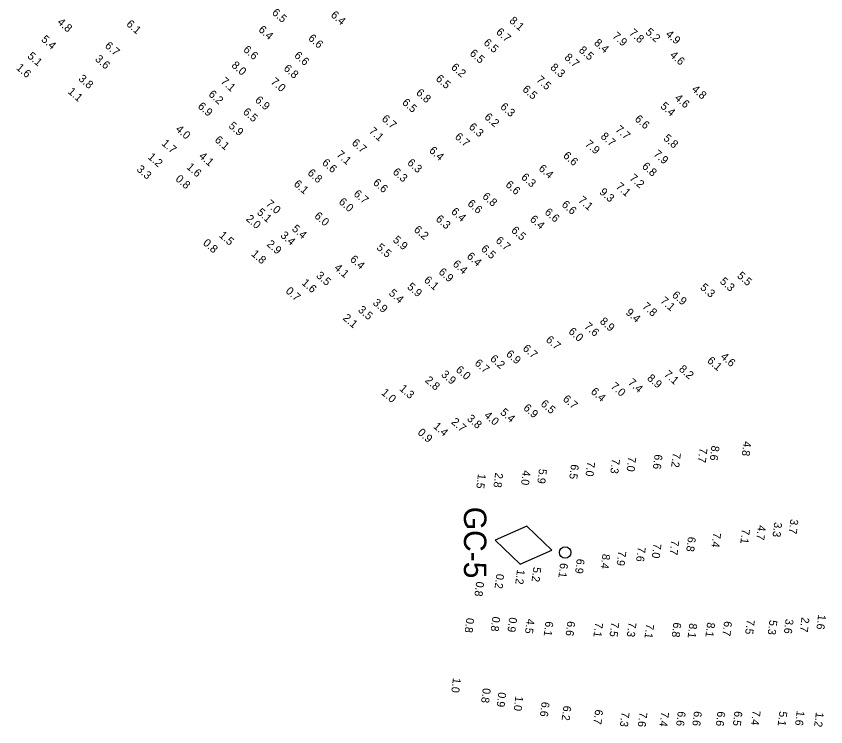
# Model space of a CAD drawing. Extents: x 815385 to 820851, y 582449 to 604245.
# Drawn here: x 819236 to 819741, y 595755 to 596198 of the extents above; entities that cross this region are included whole.
import ezdxf

# ---------------------------------------------------------------- set-up
doc = ezdxf.new("R2010")
doc.units = 0
doc.layers.add('V-CHAN-AIDS', color=7, linetype='Continuous')
doc.layers.add('V-TOPO-SOUN-020209', color=7, linetype='Continuous')

msp = doc.modelspace()

# ---------------------------------------------------------------- linework, layer by layer
at = {"layer": 'V-CHAN-AIDS'}
msp.add_lwpolyline([(819570.13, 595865), (819554.48, 595879.94), (819534.67, 595871.25), (819550.32, 595856.31)], close=True, dxfattribs=at)
msp.add_circle((819578.4, 595863.54), 3.6, dxfattribs=at)

# ---------------------------------------------------------------- texts
msp.add_text('GC-5', height=14, rotation=270, dxfattribs=at).set_placement((819515.17, 595892.08))
at = {"layer": 'V-TOPO-SOUN-020209'}
for s, rotation, p in [('6.5', 319.002, (819394.89, 596199.97)), ('6.4', 319.002, (819431.62, 596198.53)), ('4.8', 319.002, (819260.85, 596194.02)), ('6.1', 319.002, (819303.93, 596192.87)), ('8.1', 319.002, (819543.14, 596194.95)), ('6.4', 319.002, (819386.44, 596189.31)), ('6.7', 319.002, (819534.88, 596187.88)), ('7.9', 319.002, (819607.45, 596185.32)), ('7.8', 319.002, (819618.01, 596187.29)), ('5.2', 319.002, (819628.18, 596187.76)), ('5.4', 319.002, (819250.8, 596183.28)), ('6.6', 319.002, (819417.55, 596183.98)), ('6.5', 319.002, (819527.04, 596181.17)), ('8.4', 319.002, (819596.05, 596181.07)), ('4.9', 319.002, (819640.76, 596186.5)), ('6.7', 319.002, (819290.55, 596179.29)), ('6.6', 319.002, (819376.96, 596176.84)), ('8.5', 319.002, (819586.56, 596176.52)), ('5.1', 319.002, (819242.21, 596172.84)), ('3.6', 319.002, (819284.45, 596171)), ('6.6', 319.002, (819408.81, 596173.22)), ('6.5', 319.002, (819518.38, 596174.55)), ('8.7', 319.002, (819577.54, 596171.98)), ('4.6', 319.002, (819643.39, 596173.43)), ('8.0', 319.002, (819369.62, 596167.07)), ('6.2', 319.002, (819506.77, 596165.84)), ('8.3', 319.002, (819568.72, 596165.73)), ('1.6', 319.002, (819235.17, 596165.58)), ('6.8', 319.002, (819402.18, 596165.13)), ('3.8', 319.002, (819274.05, 596158.75)), ('7.1', 319.002, (819362.89, 596157)), ('7.0', 319.002, (819394.17, 596156.8)), ('6.5', 319.002, (819497.2, 596158.71)), ('7.5', 319.002, (819559.93, 596158.02)), ('6.5', 319.002, (819551.33, 596152.09)), ('4.8', 319.002, (819657.03, 596152.16)), ('1.1', 319.002, (819267.43, 596150.68)), ('6.2', 319.002, (819355.27, 596149.01)), ('6.9', 319.002, (819384.32, 596145.37)), ('6.8', 319.002, (819484.9, 596149.92)), ('4.6', 319.002, (819646.4, 596146.65)), ('6.9', 319.002, (819348.57, 596141.5)), ('6.5', 319.002, (819476.17, 596143.85)), ('6.3', 319.002, (819537.45, 596141.2)), ('5.4', 319.002, (819637.49, 596141.55)), ('6.5', 319.002, (819376.77, 596137.96)), ('6.7', 319.002, (819463.44, 596133.65)), ('6.2', 319.002, (819527.55, 596134.78)), ('6.6', 319.002, (819621.43, 596133.56)), ('4.0', 319.002, (819334.73, 596127.22)), ('5.9', 319.002, (819367.83, 596129.27)), ('7.1', 319.002, (819455.42, 596126)), ('6.3', 319.002, (819517.85, 596128.62)), ('7.7', 319.002, (819609.38, 596127)), ('6.1', 319.002, (819359.11, 596120.49)), ('6.7', 319.002, (819509.13, 596122.44)), ('8.7', 319.002, (819600.17, 596122.69)), ('5.8', 319.002, (819639.3, 596121.56)), ('1.7', 319.002, (819326.01, 596118.34)), ('6.7', 319.002, (819444.75, 596118.65)), ('7.9', 319.002, (819590.41, 596117.91)), ('7.1', 319.002, (819435.16, 596111.36)), ('6.4', 319.002, (819493.02, 596113.87)), ('6.6', 319.002, (819576.73, 596110.66)), ('7.9', 319.002, (819633.17, 596111.67)), ('1.2', 319.002, (819317.38, 596109.87)), ('4.1', 319.002, (819349.3, 596110.38)), ('6.6', 319.002, (819426.16, 596106.24)), ('6.3', 319.002, (819479.38, 596106.23)), ('3.3', 319.002, (819310.37, 596102.2)), ('1.6', 319.002, (819341.56, 596103.58)), ('6.8', 319.002, (819417.1, 596099.9)), ('6.3', 319.002, (819470.3, 596100.47)), ('6.4', 319.002, (819561.41, 596102.61)), ('6.8', 319.002, (819625.96, 596103.99)), ('0.8', 319.002, (819334.64, 596096.15)), ('6.3', 319.002, (819550.51, 596097.23)), ('7.2', 319.002, (819618.17, 596096.66)), ('6.1', 319.002, (819408.51, 596092.98)), ('6.6', 319.002, (819458.02, 596093.8)), ('6.6', 319.002, (819540.74, 596092.53)), ('7.1', 319.002, (819609.64, 596091.4)), ('6.7', 319.002, (819445.91, 596086.83)), ('6.8', 319.002, (819526.27, 596085.2)), ('9.3', 319.002, (819599.42, 596087.93)), ('7.0', 319.002, (819391.07, 596080.61)), ('6.0', 319.002, (819436.58, 596081.84)), ('6.6', 319.002, (819517, 596080.73)), ('6.6', 319.002, (819575.82, 596080.15)), ('7.1', 319.002, (819586.19, 596082.82)), ('5.1', 319.002, (819385.53, 596075.29)), ('6.4', 319.002, (819506.74, 596075.71)), ('6.6', 319.002, (819565.17, 596075.37)), ('2.0', 319.002, (819378.66, 596071.28)), ('6.0', 319.002, (819421.35, 596073)), ('6.3', 319.002, (819497.19, 596071.11)), ('6.4', 319.002, (819555.98, 596070.97)), ('5.4', 319.002, (819407.34, 596065.03)), ('1.5', 319.002, (819361.85, 596060.95)), ('3.4', 319.002, (819400.2, 596060.9)), ('6.2', 319.002, (819483.51, 596064.44)), ('6.5', 319.002, (819544.3, 596064.03)), ('0.8', 319.002, (819351.81, 596056.15)), ('2.9', 319.002, (819391.6, 596055.43)), ('5.9', 319.002, (819470.41, 596058.05)), ('6.7', 319.002, (819534.56, 596057.68)), ('5.5', 319.002, (819460.22, 596053.29)), ('6.5', 319.002, (819525.45, 596052.47)), ('1.8', 319.002, (819381.97, 596049.33)), ('6.4', 319.002, (819443.61, 596045.97)), ('6.4', 319.002, (819516.56, 596047.85)), ('4.1', 319.002, (819433.75, 596040.67)), ('6.4', 319.002, (819507.75, 596042.99)), ('3.5', 319.002, (819422.46, 596035.79)), ('6.9', 319.002, (819498.94, 596038.03)), ('5.5', 319.002, (819685.37, 596035.67)), ('1.6', 319.002, (819413.46, 596031.27)), ('5.9', 319.002, (819479.34, 596028.73)), ('6.1', 319.002, (819489.81, 596032.99)), ('5.3', 319.002, (819674.61, 596032.18)), ('0.7', 319.002, (819403.44, 596026.17)), ('5.4', 319.002, (819467.92, 596024.79)), ('5.3', 319.002, (819662.35, 596028.36)), ('7.1', 319.002, (819637.41, 596020)), ('6.9', 319.002, (819644.7, 596023.61)), ('3.5', 319.002, (819448.64, 596014.41)), ('3.9', 319.002, (819457.87, 596018.83)), ('7.8', 319.002, (819626.14, 596016.58)), ('2.1', 319.002, (819439.18, 596009.34)), ('9.4', 319.002, (819615.8, 596012.77)), ('7.6', 319.002, (819589.91, 596004.09)), ('8.9', 319.002, (819599.63, 596007.2)), ('6.0', 319.002, (819580.06, 596000.89)), ('6.7', 319.002, (819565.93, 595995.73)), ('6.7', 319.002, (819551.49, 595990.3)), ('6.2', 319.002, (819531.11, 595983.84)), ('6.9', 319.002, (819541.09, 595986.8)), ('4.6', 319.002, (819675.05, 595985.16)), ('6.7', 319.002, (819521.47, 595981.12)), ('6.1', 319.002, (819666.69, 595982.65)), ('3.9', 319.002, (819500.56, 595974.1)), ('6.0', 319.002, (819509.69, 595976.96)), ('7.1', 319.002, (819639.72, 595974.1)), ('8.2', 319.002, (819649.03, 595977.41)), ('2.8', 319.002, (819490.49, 595970.45)), ('7.4', 319.002, (819617.24, 595968.99)), ('8.9', 319.002, (819629.17, 595971.73)), ('1.3', 319.002, (819474.51, 595965.23)), ('6.4', 319.002, (819594.03, 595963.34)), ('7.0', 319.002, (819606.44, 595966.62)), ('1.0', 319.002, (819463.15, 595962.67)), ('6.7', 319.002, (819576.56, 595958.73)), ('6.5', 319.002, (819562.69, 595955.73)), ('5.4', 319.002, (819537.46, 595950.39)), ('6.9', 319.002, (819551.87, 595953.17)), ('2.7', 319.002, (819506.87, 595944.43)), ('3.8', 319.002, (819516.68, 595946.51)), ('4.0', 319.002, (819527.39, 595948.51)), ('1.4', 319.002, (819495.66, 595941.72)), ('0.9', 319.002, (819485.85, 595937.81)), ('4.8', 262.822, (819689.78, 595933.23)), ('7.7', 262.822, (819662.32, 595929.04)), ('8.6', 262.822, (819669.84, 595930.46)), ('7.3', 262.822, (819607.7, 595922.28)), ('7.0', 262.822, (819617.85, 595923.55)), ('6.6', 262.822, (819634.31, 595925.03)), ('7.2', 262.822, (819645.72, 595926.1)), ('6.5', 262.822, (819582.07, 595918.81)), ('7.0', 262.822, (819592.18, 595920.51)), ('1.5', 262.822, (819524, 595912.93)), ('2.8', 262.822, (819534.73, 595913.55)), ('4.0', 262.822, (819551.96, 595915.08)), ('5.9', 262.822, (819562.1, 595916.03)), ('4.7', 262.822, (819698.86, 595880.75)), ('3.3', 262.822, (819709, 595882.65)), ('3.7', 262.822, (819719.11, 595884.58)), ('7.1', 262.822, (819688.87, 595878.43)), ('7.7', 262.822, (819644.68, 595871.48)), ('6.8', 262.822, (819655.1, 595873.56)), ('7.4', 262.822, (819670.83, 595876.17)), ('7.6', 262.822, (819623.78, 595867.25)), ('7.0', 262.822, (819633.59, 595869.43)), ('8.4', 262.822, (819601.68, 595862.84)), ('7.9', 262.822, (819611.62, 595864.7)), ('6.1', 262.822, (819575.3, 595857.15)), ('6.9', 262.822, (819585.67, 595859.84)), ('1.2', 262.822, (819548.38, 595853.12)), ('5.2', 262.822, (819558.53, 595854.67)), ('0.8', 262.822, (819522.87, 595845.59)), ('0.2', 262.822, (819535.44, 595850.43)), ('0.8', 262.822, (819516.73, 595822.9)), ('0.8', 262.822, (819532.97, 595823.74)), ('0.9', 262.822, (819543.47, 595823.27)), ('4.5', 262.822, (819554.41, 595822.35)), ('6.1', 262.822, (819566.13, 595820.78)), ('6.6', 262.822, (819579.79, 595820.88)), ('8.1', 262.822, (819667.1, 595820.13)), ('6.7', 262.822, (819677.71, 595820.87)), ('7.5', 262.822, (819691.89, 595821.89)), ('5.3', 262.822, (819706, 595821.62)), ('3.6', 262.822, (819716.1, 595822.29)), ('2.7', 262.822, (819726.06, 595823.3)), ('1.6', 262.822, (819736.41, 595824.93)), ('7.1', 262.822, (819597.14, 595820.09)), ('7.5', 262.822, (819607.22, 595820.34)), ('7.3', 262.822, (819618.01, 595820.24)), ('7.1', 262.822, (819629.05, 595819.26)), ('6.8', 262.822, (819646.05, 595820.09)), ('8.1', 262.822, (819656, 595819.58)), ('1.0', 262.822, (819508.38, 595785.48)), ('0.8', 262.822, (819527.02, 595779.09)), ('0.9', 262.822, (819536.7, 595776.52)), ('1.0', 262.822, (819547.35, 595774.1)), ('6.6', 262.822, (819563.75, 595770.51)), ('6.2', 262.822, (819577.35, 595768.11)), ('6.7', 262.822, (819597.15, 595765.7)), ('6.6', 262.822, (819648.79, 595764.63)), ('6.6', 262.822, (819658.9, 595764.68)), ('6.5', 262.822, (819684.2, 595764.71)), ('7.4', 262.822, (819695.55, 595765.16)), ('5.1', 262.822, (819712.2, 595764.64)), ('1.6', 262.822, (819723.05, 595764.93)), ('7.3', 262.822, (819613.67, 595764.19)), ('7.6', 262.822, (819624.81, 595764.09)), ('7.4', 262.822, (819638.35, 595764.3)), ('6.6', 262.822, (819673.54, 595764.57)), ('1.2', 262.822, (819735.01, 595764.06))]:
    msp.add_text(s, height=5, rotation=rotation, dxfattribs=at).set_placement(p)

doc.saveas('drawing.dxf')
